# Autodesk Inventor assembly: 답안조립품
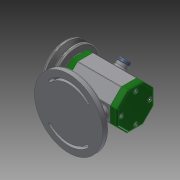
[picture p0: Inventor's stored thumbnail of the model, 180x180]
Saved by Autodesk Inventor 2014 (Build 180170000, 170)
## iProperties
Created: 2017-06
Part Number: 답안조립품
Document SubType Name: Assembly
Designer: net
Author: net
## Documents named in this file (14)
- C:\Users\net\Desktop\470607V1014\답안조립품.iam
- C:\Users\net\Desktop\470607V1014\답안부품.ipt
- C:\Users\net\Desktop\470607V1014\축.ipt
- C:\Users\net\Desktop\470607V1014\키 3 x 3 x 12.ipt
- C:\Users\net\Desktop\470607V1014\V벨트풀리.ipt
- C:\Users\net\Desktop\470607V1014\와셔 8x17.ipt
- C:\Users\net\Desktop\470607V1014\스프링와셔 8.ipt
- C:\Users\net\Desktop\470607V1014\너트 M 8.ipt
- C:\Users\net\Desktop\470607V1014\앞커버.ipt
- C:\Users\net\Desktop\470607V1014\볼트 M4 x 12.ipt
- C:\Users\net\Desktop\470607V1014\베어링 15 x 32 x 9.ipt
- C:\Users\net\Desktop\470607V1014\뒤커버.ipt
- C:\Users\net\Desktop\470607V1014\오일 실 15 25 7.ipt
- C:\Users\net\Desktop\470607V1014\고무캡.ipt
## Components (2 placed, 2 different names)
1. V벨트풀리:1
2. 고무캡:1
